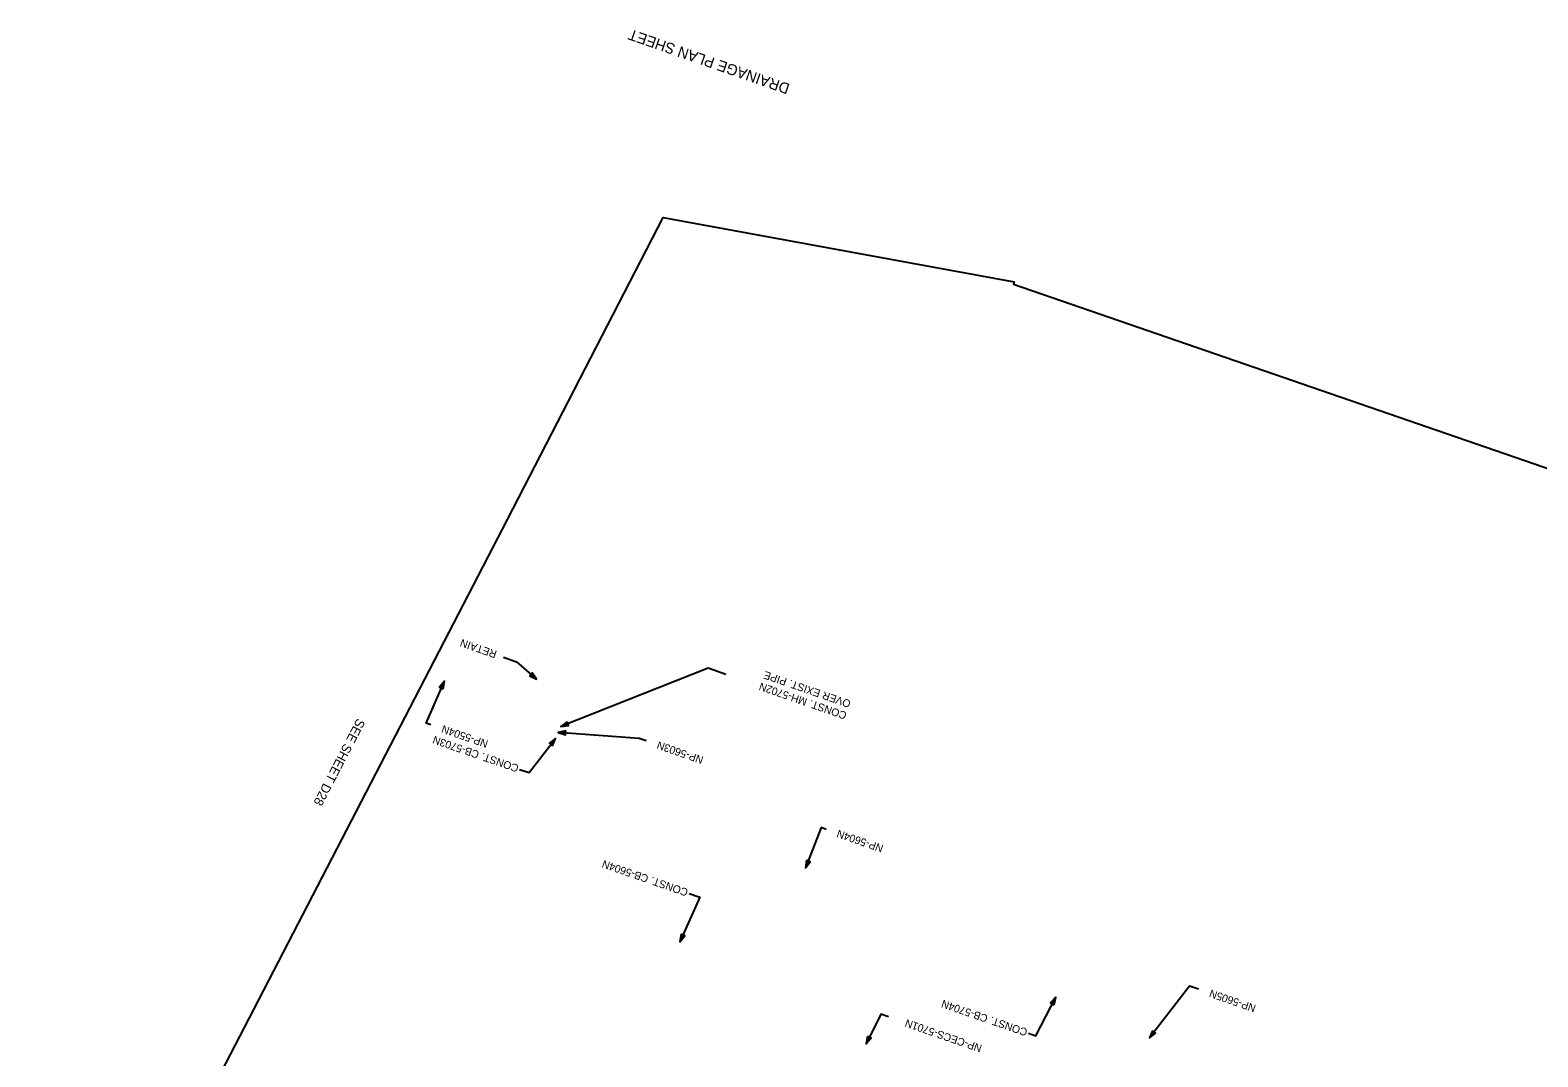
# Model space of a CAD drawing. Extents: x 1607775 to 1609652, y 1093977 to 1095566.
# Drawn here: x 1607775 to 1608751, y 1094739 to 1095404 of the extents above; entities that cross this region are included whole.
import ezdxf

# ---------------------------------------------------------------- set-up
doc = ezdxf.new("R2010")
doc.units = 0
for name, color, linetype in [('RD_HY_Area_SS1', 7, 'Continuous'), ('RD_PD_DR_ErosCtrl', 7, 'Continuous'), ('RD_PD_MedBWall', 7, 'Continuous'), ('RD_TX_EndArea', 7, 'Continuous')]:
    doc.layers.add(name, color=color, linetype=linetype)

msp = doc.modelspace()

# ---------------------------------------------------------------- linework, layer by layer
at = {"layer": 'RD_PD_DR_ErosCtrl'}
msp.add_lwpolyline([(1609319.26, 1094082.92), (1609257.16, 1093976.84), (1607774.66, 1094490.39), (1607913.49, 1094758.18), (1608083.85, 1095087.22), (1608184.77, 1095282.94), (1608412.15, 1095241.23), (1608411.67, 1095239.7), (1609329.12, 1094923.25), (1609333.64, 1094914.63), (1609347.07, 1094917.06), (1609439, 1094885.35), (1609428.8, 1094854.27), (1609615.32, 1094789.49), (1609546.66, 1094678.85), (1609459.72, 1094656.09), (1609449.74, 1094513.93), (1609414.43, 1094518.3), (1609397.89, 1094407.56), (1609403.67, 1094397.48), (1609379.74, 1094297.75), (1609387.82, 1094283.49), (1609353.45, 1094193.74), (1609389.72, 1094179.44)], close=True, dxfattribs=at)
msp.add_lwpolyline([(1609319.26, 1094082.92), (1609257.16, 1093976.84), (1607774.66, 1094490.39), (1607913.49, 1094758.18), (1608083.85, 1095087.22), (1608184.77, 1095282.94), (1608412.15, 1095241.23), (1608411.67, 1095239.7), (1609329.12, 1094923.25), (1609333.64, 1094914.63), (1609347.07, 1094917.06), (1609439, 1094885.35), (1609428.8, 1094854.27), (1609615.32, 1094789.49), (1609546.66, 1094678.85), (1609459.72, 1094656.09), (1609449.74, 1094513.93), (1609414.43, 1094518.3), (1609397.89, 1094407.56), (1609403.67, 1094397.48), (1609379.74, 1094297.75), (1609387.82, 1094283.49), (1609353.45, 1094193.74), (1609389.72, 1094179.44)], close=True, dxfattribs=at)
msp.add_lwpolyline([(1609319.26, 1094082.92), (1609257.16, 1093976.84), (1607774.66, 1094490.39), (1607913.49, 1094758.18), (1608083.85, 1095087.22), (1608184.77, 1095282.94), (1608412.15, 1095241.23), (1608411.67, 1095239.7), (1609329.12, 1094923.25), (1609333.64, 1094914.63), (1609347.07, 1094917.06), (1609439, 1094885.35), (1609428.8, 1094854.27), (1609615.32, 1094789.49), (1609546.66, 1094678.85), (1609459.72, 1094656.09), (1609449.74, 1094513.93), (1609414.43, 1094518.3), (1609397.89, 1094407.56), (1609403.67, 1094397.48), (1609379.74, 1094297.75), (1609387.82, 1094283.49), (1609353.45, 1094193.74), (1609389.72, 1094179.44)], close=True, dxfattribs=at)
msp.add_lwpolyline([(1609319.26, 1094082.92), (1609257.16, 1093976.84), (1607774.66, 1094490.39), (1607913.49, 1094758.18), (1608083.85, 1095087.22), (1608184.77, 1095282.94), (1608412.15, 1095241.23), (1608411.67, 1095239.7), (1609329.12, 1094923.25), (1609333.64, 1094914.63), (1609347.07, 1094917.06), (1609439, 1094885.35), (1609428.8, 1094854.27), (1609615.32, 1094789.49), (1609546.66, 1094678.85), (1609459.72, 1094656.09), (1609449.74, 1094513.93), (1609414.43, 1094518.3), (1609397.89, 1094407.56), (1609403.67, 1094397.48), (1609379.74, 1094297.75), (1609387.82, 1094283.49), (1609353.45, 1094193.74), (1609389.72, 1094179.44)], close=True, dxfattribs=at)
msp.add_lwpolyline([(1609319.26, 1094082.92), (1609257.16, 1093976.84), (1607774.66, 1094490.39), (1607913.49, 1094758.18), (1608083.85, 1095087.22), (1608184.77, 1095282.94), (1608412.15, 1095241.23), (1608411.67, 1095239.7), (1609329.12, 1094923.25), (1609333.64, 1094914.63), (1609347.07, 1094917.06), (1609439, 1094885.35), (1609428.8, 1094854.27), (1609615.32, 1094789.49), (1609546.66, 1094678.85), (1609459.72, 1094656.09), (1609449.74, 1094513.93), (1609414.43, 1094518.3), (1609397.89, 1094407.56), (1609403.67, 1094397.48), (1609379.74, 1094297.75), (1609387.82, 1094283.49), (1609353.45, 1094193.74), (1609389.72, 1094179.44)], close=True, dxfattribs=at)
msp.add_lwpolyline([(1609319.26, 1094082.92), (1609257.16, 1093976.84), (1607774.66, 1094490.39), (1607913.49, 1094758.18), (1608083.85, 1095087.22), (1608184.77, 1095282.94), (1608412.15, 1095241.23), (1608411.67, 1095239.7), (1609329.12, 1094923.25), (1609333.64, 1094914.63), (1609347.07, 1094917.06), (1609439, 1094885.35), (1609428.8, 1094854.27), (1609615.32, 1094789.49), (1609546.66, 1094678.85), (1609459.72, 1094656.09), (1609449.74, 1094513.93), (1609414.43, 1094518.3), (1609397.89, 1094407.56), (1609403.67, 1094397.48), (1609379.74, 1094297.75), (1609387.82, 1094283.49), (1609353.45, 1094193.74), (1609389.72, 1094179.44)], close=True, dxfattribs=at)
at = {"layer": 'RD_PD_MedBWall'}
for points in [[(1608081.37, 1094997.99), (1608089.76, 1094995.09), (1608102.62, 1094983.73)], [(1608225.35, 1094986.9), (1608213.94, 1094990.85), (1608118.45, 1094953.21)], [(1608034.22, 1094954.26), (1608031.32, 1094955.27), (1608043.05, 1094982.58)], [(1608091.79, 1094925.38), (1608097.99, 1094923.24), (1608115.09, 1094945.28)], [(1608173.74, 1094943.84), (1608169.29, 1094945.38), (1608116.81, 1094949.32)], [(1608290.27, 1094886.51), (1608287.08, 1094887.62), (1608277.06, 1094861.52)], [(1608201.52, 1094844.98), (1608208.55, 1094842.54), (1608195.63, 1094813.74)], [(1608421.37, 1094754.4), (1608426.3, 1094752.7), (1608439.07, 1094777.81)], [(1608531.65, 1094782.99), (1608525.8, 1094785.01), (1608499.85, 1094751.44)], [(1608330.7, 1094765.11), (1608325.8, 1094766.8), (1608316.19, 1094747.46)]]:
    msp.add_lwpolyline(points, dxfattribs=at)
for points in [[(1608042.33, 1094977.63), (1608043.05, 1094982.58), (1608039.96, 1094978.65)], [(1608098.14, 1094985.96), (1608102.62, 1094983.73), (1608099.85, 1094987.9)], [(1608122.47, 1094956.19), (1608118.45, 1094953.21), (1608123.42, 1094953.78)], [(1608113.15, 1094940.67), (1608115.09, 1094945.28), (1608111.1, 1094942.26)], [(1608121.72, 1094950.25), (1608116.81, 1094949.32), (1608121.53, 1094947.67)], [(1608277.58, 1094866.49), (1608277.06, 1094861.52), (1608280, 1094865.56)], [(1608196.42, 1094818.67), (1608195.63, 1094813.74), (1608198.78, 1094817.61)], [(1608438.03, 1094772.92), (1608439.07, 1094777.81), (1608435.73, 1094774.09)], [(1608501.78, 1094756.05), (1608499.85, 1094751.44), (1608503.83, 1094754.47)], [(1608317.18, 1094752.36), (1608316.19, 1094747.46), (1608319.5, 1094751.21)]]:
    msp.add_lwpolyline(points, close=True, dxfattribs=at)

# ---------------------------------------------------------------- texts
at = {"layer": 'RD_HY_Area_SS1'}
msp.add_text('SEE SHEET D28', height=6, rotation=242.57187, dxfattribs=at).set_placement((1607986.6, 1094958.83))
at = {"layer": 'RD_PD_MedBWall'}
for s, p in [('RETAIN', (1608077.46, 1095001.99)), ('CONST. MH-5702N', (1608304.15, 1094962.26)), ('OVER EXIST. PIPE', (1608306.76, 1094969.82)), ('NP-5504N', (1608071.77, 1094943.9)), ('CONST. CB-5703N', (1608091.66, 1094928.07)), ('NP-5603N', (1608211.29, 1094933.48)), ('NP-5604N', (1608327.82, 1094876.16)), ('CONST. CB-5604N', (1608201.39, 1094847.67)), ('CONST. CB-5704N', (1608421.24, 1094757.09)), ('NP-5605N', (1608569.2, 1094772.63)), ('NP-CECS-5701N', (1608391.69, 1094746.63))]:
    msp.add_text(s, height=5, rotation=160.90131, dxfattribs=at).set_placement(p)
at = {"layer": 'RD_TX_EndArea'}
msp.add_text('DRAINAGE PLAN SHEET', height=6.9833, rotation=160.90294, dxfattribs=at).set_placement((1608267.31, 1095369.22))

doc.saveas('drawing.dxf')
